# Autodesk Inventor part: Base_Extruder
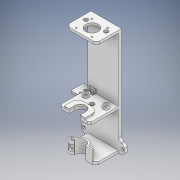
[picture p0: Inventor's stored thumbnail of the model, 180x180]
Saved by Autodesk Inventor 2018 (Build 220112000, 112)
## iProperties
Part Number: Base_Extruder
Material: Plástico ABS
Document SubType Name: Modeling
Designer: ULISES
Density: 1.06 g/cm^3
Appearance: Valor por defecto(1)
Mass: 170.779 g
Surface Area: 663.504 cm^2
Volume: 161.112 cm^3
Author: ULISES
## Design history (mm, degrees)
sketch "Boceto1"
  geometry: L1 (0, 0)-(60, 0); L2 (60, 0)-(60, 49); L3 (60, 49)-(0, 49); L4 (0, 49)-(0, 0); C1 r 1.6 at (50, 29); C2 r 1.6 at (10, 29); C3 r 12.5 at (30, 21); C4 r 13.5 at (30, -2); C5 r 1.6 at (45.5, 36.5); C6 r 1.6 at (14.5, 36.5); C7 r 1.6 at (45.5, 5.5); C8 r 1.6 at (14.5, 5.5)
  constraints: 8 centre point, 8 end point, 2 horizontal, 2 parallel, 1 horizontal alignment, 1 perpendicular, 1 vertical, 1 vertical alignment, 6 other
  dimensions: "d0" = 3.2 diameter of C1; "d1" = 3.2 diameter of C2 (= d0); "d2" = 25 diameter of C3; "d3" = 27 diameter of C4; "d10" = 20 horizontal distance of C3.centre C2.centre (= 0.5 x d15); "d14" = 60 distance of L2.end L3.end; "d15" = 40 distance of C2.centre C1.centre; "d16" = 10 distance from line of L4 C2.centre (= 0.5 x d14 - 0.5 x d15); "d17" = 3.2 diameter of C5; "d20" = 31 distance of C5.centre C6.centre; "d23" = 31 distance of C5.centre C7.centre; "d26" = 15.5 horizontal distance of C5.centre C3.centre (= 0.5 x d20); "d27" = 15.5 horizontal distance of C5.centre C3.centre (= 0.5 x d23); "d47" = 23 distance of C4.centre C3.centre; "d48" = 49 distance of L3.end L1.start; "d50" = 28 distance from line of L3 C3.centre; "d51" = 20 distance from line of L3 C1.centre; "d52" = 8 vertical distance of C3.centre C1.centre (derived)
extrude "Extrusión1" new body sketch "Boceto1" distance "d28" = 5; taper "d29" = 0 deg
sketch "Boceto2"
  geometry: C1 r 1.6 at (10, 29) reference; C2 r 1.6 at (50, 29) reference; C3 r 4.15 at (10, 29); C4 r 4.15 at (50, 29); 1 further point
  constraints: 2 centre point, 2 coincident
  dimensions: "d32" = 8.3 diameter of C3; "d33" = 8.3 diameter of C4
extrude "Extrusión2" cut sketch "Boceto2" distance "d30" = 6; taper "d31" = 0 deg
sketch "Boceto3"
  geometry: L1 (0, 0)-(-60, 0) reference; L2 (0, 49)-(0, 0) reference; L3 (-60, 49)-(0, 49) reference; L4 (-60, 0)-(-60, 49) reference; L5 (-60, 0)-(-60, 49) reference; L6 (-60, 49)-(0, 49); L7 (0, 49)-(0, 43); L8 (0, 43)-(-60, 43); L9 (-60, 43)-(-60, 49); C1 r 12.5 at (-30, 21) reference; C2 r 1.6 at (-14.5, 5.5) reference; C3 r 1.6 at (-45.5, 5.5) reference; C4 r 1.6 at (-14.5, 36.5) reference; C5 r 1.6 at (-45.5, 36.5) reference; 1 further point
  constraints: 8 end point, 2 parallel, 1 horizontal, 1 perpendicular, 1 point on line
  dimensions: "d34" = 6 distance between parallel lines of L3 L8
extrude "Extrusión3" join sketch "Boceto3" distance "d35" = 125; taper "d36" = 0 deg
sketch "Boceto4"
  geometry: L1 (0, 43)-(-60, 43) reference; L2 (-60, 0)-(-60, 43) reference; L3 (0, 0)-(-60, 0) reference; L4 (0, 43)-(0, 0) reference; L5 (0, 43)-(0, 49) reference; L6 (0, 49)-(-60, 49) reference; L7 (-60, 49)-(-60, 43) reference; L8 (-60, 43)-(0, 43) reference; L9 (-60, 0)-(-60, -13); L10 (-60, -13)-(0, -13); L11 (0, -13)-(0, 0); L12 (0, 0)-(-19.285, 0); L13 (-40.715, 0)-(-60, 0); L14 (0, 49)-(0, 0) reference; L15 (0, 0)-(0, 49); L16 (0, 49)-(-60, 49); L17 (-60, 49)-(-60, 0); L18 (-60, 0)-(-40.715, 0); L19 (-19.285, 0)-(0, 0); L20 (-30, -2)-(-40.9, -2); L21 (-40.9, -2)-(-40.9, -13); L22 (-40.9, -13)-(-30, -13); L23 (-30, -13)-(-30, -2); L24 (-30, -2)-(-19.1, -2); L25 (-19.1, -2)-(-19.1, -13); L26 (-19.1, -13)-(-30, -13); L27 (-30, -13)-(-30, -2); C1 r 12.5 at (-30, 21) reference; C2 r 1.6 at (-14.5, 5.5) reference; C3 r 1.6 at (-45.5, 5.5) reference; C4 r 1.6 at (-14.5, 36.5) reference; C5 r 1.6 at (-45.5, 36.5) reference; C6 r 4.5 at (-30, 21); A1 r 10.9 centre (-30, -2) between (-19.285, 0) and (-40.715, 0)
  constraints: 36 end point, 10 parallel, 6 horizontal, 6 perpendicular, 2 centre point, 2 collinear, 2 point on circle, 2 tangent, 1 coincident, 1 point on line, 1 vertical alignment
  dimensions: "d37" = 9 diameter of C6; "d54" = 13 distance of L9.start L9.end; "d55" = 60 distance of L9.end L10.end; "d62" = 23 distance of L20.start C1.centre; "d63" = 21.8 diameter of A1
extrude "Extrusión4" join sketch "Boceto4" distance "d39" = 5; taper "d40" = 0 deg
sketch "Boceto5"
  geometry: C1 r 4.15 at (-10, 29) reference; C2 r 4.15 at (-50, 29) reference; C3 r 6.15 at (-10, 29); C4 r 6.15 at (-50, 29); 1 further point
  constraints: 2 centre point
  dimensions: "d175" = 2 radial gap between concentric circles of C3 C1; "d176" = 2 radial gap between concentric circles of C2 C4
extrude "Extrusión5" join sketch "Boceto5" distance "d41" = 10; taper "d42" = 0 deg
sketch "Boceto6"
  geometry: L1 (-60, 43)-(0, 43) reference; L2 (-60, 43)-(0, 43); L3 (0, 43)-(0, 49); L4 (0, 49)-(-60, 49); L5 (-60, 49)-(-60, 43); L6 (-60, -13)-(-40.9, -13) reference; L7 (0, -13)-(0, 49) reference; L8 (0, 49)-(-60, 49) reference; L9 (-60, 49)-(-60, -13) reference; L10 (-40.9, -13)-(-40.9, -2) reference; L11 (-19.1, -2)-(-19.1, -13) reference; L12 (-19.1, -13)-(0, -13) reference; L13 (-40.9, -2)-(-19.1, -2) reference; C1 r 4.5 at (-30, 21) reference; 1 further point
  constraints: 8 end point, 2 parallel, 1 horizontal, 1 perpendicular
extrude "Extrusión6" join sketch "Boceto6" distance "d43" = 70; taper "d44" = 0 deg
sketch "Boceto7"
  geometry: L1 (0, 43)-(-60, 43) reference; L2 (-60, 43)-(0, 43) reference; L3 (0, 43)-(0, 49) reference; L4 (0, 49)-(-60, 49) reference; L5 (-60, 49)-(-60, 43) reference; L6 (-60, -13)-(-40.9, -13) reference; L7 (-60, 43)-(-60, -13) reference; L8 (0, -13)-(0, 43) reference; L9 (-40.9, -13)-(-40.9, -2) reference; L10 (-19.1, -2)-(-19.1, -13) reference; L11 (-60, -13)-(-40.9, -13) reference; L12 (-40.9, -2)-(-60, -2); L13 (-19.1, -2)-(0, -2); L14 (-60, 49)-(0, 49) reference; L15 (0, -2)-(0, 49); L16 (0, 49)-(-60, 49); L17 (-60, 49)-(-60, -2); L18 (-60, -2)-(-40.9, -2); L19 (-19.1, -2)-(0, -2); L20 (-19.1, -13)-(0, -13) reference; L21 (-40.9, -2)-(-19.1, -2) reference; C1 r 4.5 at (-30, 21) reference; A1 r 10.9 centre (-30, -2) between (-19.1, -2) and (-40.9, -2); 1 further point
  constraints: 14 end point, 3 horizontal, 3 parallel, 2 perpendicular, 2 point on circle, 1 centre point
  dimensions: "d177" = 10.9 radius of A1
extrude "Extrusión7" join sketch "Boceto7" distance "d45" = 5; taper "d46" = 0 deg
sketch "Boceto8"
  geometry: C1 r 1.6 at (-45.5, 5.5) reference; C2 r 1.6 at (-45.5, 36.5) reference; C3 r 1.6 at (-14.5, 36.5) reference; C4 r 1.6 at (-14.5, 5.5) reference; C5 r 3 at (-45.5, 5.5); C6 r 3 at (-45.5, 36.5); C7 r 3 at (-14.5, 36.5); C8 r 1.6 at (-14.5, 5.5) reference; C9 r 3 at (-14.5, 5.5); 1 further point
  constraints: 4 centre point, 4 coincident
  dimensions: "d56" = 6 diameter of C5; "d57" = 6 diameter of C6; "d58" = 6 diameter of C7; "d59" = 6 diameter of C9
extrude "Extrusión8" cut sketch "Boceto8" distance "d60" = 2.5; taper "d61" = 0 deg
sketch "Boceto9"
  geometry: L1 (18.5, 1)-(38.5, 1); L2 (38.5, 11)-(21.5, 11); L3 (48.5, 1)-(48.5, -13); L4 (11.5, -13)-(11.5, 1); L5 (9.5, -13)-(9.5, 1); L6 (21.5, 13)-(38.5, 13); L7 (50.5, 1)-(50.5, -13); L8 (48.5, -13)-(50.5, -13); L9 (9.5, -13)-(11.5, -13); L10 (19.1, -2)-(40.9, -2) reference; L11 (19.1, -13)-(19.1, -2) reference; L12 (19.1, -13)-(0, -13) reference; L13 (60, -13)-(40.9, -13) reference; L14 (40.9, -2)-(40.9, -13) reference; A1 r 10 centre (38.5, 1) between (48.5, 1) and (38.5, 11); A2 r 10 centre (21.5, 1) between (21.5, 11) and (11.5, 1); A3 r 12 centre (21.5, 1) between (21.5, 13) and (9.5, 1); A4 r 12 centre (38.5, 1) between (50.5, 1) and (38.5, 13); 1 further point
  constraints: 19 end point, 8 point on circle, 4 centre point, 4 tangent, 2 collinear, 2 parallel, 1 point on line, 4 other
  dimensions: "d64" = 20 distance of L1.start L1.end; "d66" = 2 radial gap between concentric circles of A1 A4; "d183" = 37 distance between parallel lines of L3 L4; "d184" = 21.8 distance between parallel lines of L14 L11 (derived); "d185" = 7.6 distance between parallel lines of L4 L11 (= 0.5 x d183 - 0.5 x d184); "d186" = 13 distance between parallel lines of L10 L2; "d187" = 10 radius of A2; "d188" = 10 radius of A1
extrude "Extrusión9" join sketch "Boceto9" distance "d67" = 2.2; taper "d68" = 0 deg
sketch "Boceto11" dims "d104" = 10.9 (derived)
  geometry: L1 (44, -2)-(54, -2); L2 (54, -2)-(54, 1); L3 (54, 1)-(43.572, 1); L4 (44, 1)-(44, -2); L5 (19.1, -2)-(9.1, -2); L6 (9.1, -2)-(9.1, 3); L7 (9.1, 3)-(17.03, 3); L8 (19.1, -2)-(0, -2) reference; L9 (19.1, -2)-(9.1, -2); L10 (9.1, -2)-(9.1, -7); L11 (9.1, -7)-(19.1, -7); L12 (19.1, -7)-(19.1, -2); L13 (60, -2)-(40.9, -2) reference; L14 (44, -2)-(40.9, -2); A1 r 13.9 centre (30, -2) between (43.572, 1) and (17.03, 3); 2 further points
  constraints: 24 end point, 4 horizontal, 4 parallel, 3 perpendicular, 2 point on circle, 1 centre point, 1 collinear, 1 vertical, 2 other
  dimensions: "d71" = 3 dimension on A1; "d72" = 3 distance of L1.end L2.end; "d73" = 10 distance of L2.end L4.start; "d75" = 5 distance of L5.end L6.end; "d84" = 10 distance from line of L6 L5.start; "d106" = 5 distance of L9.end L10.end; "d107" = 10 distance of L10.end L11.end
extrude "Extrusión11" join sketch "Boceto11" distance "d76" = 20; taper "d77" = 0 deg
node "Plano de trabajo1"
sketch "Boceto13"
  geometry: L1 (0, 49)-(-60, 49) reference; L2 (-60, 49)-(-60, -2) reference; L3 (-60, -2)-(-40.9, -2) reference; L4 (-19.1, -2)-(0, -2) reference; L5 (0, -2)-(0, 49) reference; L6 (-9.1, -2)-(-9.1, 3) reference; L7 (-19.1, -2)-(0, -2) reference; L8 (-17.03, 3)-(-9.1, 3) reference; L9 (-9.1, 3)-(-17.03, 3); L10 (-9.1, 3)-(-9.1, -7) reference; L11 (-9.1, 3)-(-9.1, -2); L12 (-9.1, -2)-(-21.1, -2); L13 (-21.1, -2)-(-21.1, -7); L14 (-21.1, -7)-(-9.1, -7); L15 (-9.1, -7)-(-9.1, -2); C1 r 4 at (-14.1, -2); C2 r 1.7 at (-14.1, -2); A1 r 10.9 centre (-30, -2) between (-19.1, -2) and (-40.9, -2) reference; A2 r 13.9 centre (-30, -2) between (-17.03, 3) and (-43.572, 1) reference; 1 further point
  constraints: 12 end point, 2 centre point, 2 horizontal, 2 parallel, 2 perpendicular, 1 coincident, 1 collinear
  dimensions: "d85" = 0 distance from line of L4 C1.centre; "d86" = 5 distance from line of L6 C1.centre; "d87" = 8 diameter of C1; "d88" = 3.4 diameter of C2; "d90" = 12 distance between parallel lines of L10 L13; "d108" = 5 distance of L12.end L13.end
extrude "Extrusión12" cut sketch "Boceto13" distance "d91" = 12; taper "d92" = 0 deg
sketch "Boceto14"
  geometry: L1 (40.9, -2)-(54, -2) reference; L2 (54, -2)-(54, 1) reference; L3 (54, 1)-(43.572, 1) reference; L4 (17.03, 3)-(9.1, 3) reference; L5 (9.1, 3)-(9.1, -7) reference; L6 (9.1, -7)-(19.1, -7) reference; L7 (19.1, -7)-(19.1, -2) reference; C1 r 1.75 at (14.1, -2); A1 r 13.9 centre (30, -2) between (43.572, 1) and (17.03, 3) reference; A2 r 10.9 centre (30, -2) between (40.9, -2) and (19.1, -2) reference; 1 further point
  constraints: 1 centre point
  dimensions: "d93" = 5 distance from line of L4 C1.centre; "d94" = 5 distance from line of L5 C1.centre; "d95" = 3.5 diameter of C1
extrude "Extrusión13" cut sketch "Boceto14" distance "d96" = 45.5; taper "d97" = 0 deg
sketch "Boceto15"
  geometry: L1 (16.886, -3.857)-(13.884, -5.342); L2 (13.884, -5.342)-(11.098, -3.484); L3 (11.098, -3.484)-(11.314, -0.143); L4 (11.314, -0.143)-(14.316, 1.342); L5 (14.316, 1.342)-(17.102, -0.516); L6 (17.102, -0.516)-(16.886, -3.857); C1 r 1.75 at (14.1, -2) reference; 2 further points
  constraints: 12 end point, 1 coincident, 13 other
  dimensions: "d98" = 5.8 distance between parallel lines of L3 L6
extrude "Extrusión14" cut sketch "Boceto15" distance "d99" = 4; taper "d100" = 0 deg
sketch "Boceto17"
  geometry: L1 (-19.1, -7)-(-19.1, -2) reference; L2 (-9.1, -7)-(-19.1, -7) reference; L3 (-9.1, -2)-(-9.1, -7) reference; L4 (-12.35, -2)-(-9.1, -2) reference; L5 (-19.1, -2)-(-15.85, -2) reference; A1 r 1.75 centre (-14.1, -2) between (-15.85, -2) and (-12.35, -2) reference; 1 further point
extrude "Extrusión16" join sketch "Boceto17" distance "d109" = 5; taper "d110" = 0 deg
sketch "Boceto16"
  geometry: C1 r 1.75 at (-14.1, -2) reference; C2 r 3 at (-14.1, -2); 1 further point
  constraints: 1 centre point, 1 coincident
  dimensions: "d101" = 6 diameter of C2
extrude "Extrusión15" cut sketch "Boceto16" distance "d102" = 4; taper "d103" = 0 deg
fillet "Empalme1" dims "d111" = 5
chamfer "Chaflán1" distance "d112" = 6; stored, may be unused: second distance "d113" = 2, angle "d114" = 45 deg
chamfer "Chaflán2" distance "d115" = 4; stored, may be unused: second distance "d116" = 2, angle "d117" = 45 deg
chamfer "Chaflán3" distance "d118" = 6; stored, may be unused: second distance "d119" = 2, angle "d120" = 45 deg
sketch "Boceto18"
  geometry: L1 (0, -52)-(0, 0) reference; L2 (-5, -52)-(-5, 0) reference; L3 (-80, 6)-(130, 6) reference; L4 (0, -19)-(-5, -19); L5 (-5, -19)-(-5, 6); L6 (-5, 6)-(0, 6); L7 (0, 6)-(0, -19); 2 further points
  constraints: 8 end point, 3 point on line, 2 parallel, 1 horizontal, 1 perpendicular
  dimensions: "d121" = 25 distance between parallel lines of L3 L4
extrude "Extrusión17" join sketch "Boceto18" distance "d122" = 14; taper "d123" = 0 deg
sketch "Boceto19"
  geometry: L1 (0, 49)-(-14, 49) reference; L2 (0, 49)-(0, 6) reference; C1 r 1.6 at (-1.6, 29); C2 r 1.6 at (-1.6, 39); 1 further point
  constraints: 2 centre point, 1 vertical alignment
  dimensions: "d124" = 3.2 diameter of C1; "d125" = 3.2 diameter of C2; "d126" = 10 distance from line of L1 C2.centre; "d127" = 10 distance of C2.centre C1.centre; "d128" = 1.6 distance from line of L2 C2.centre (= 0.5 x d125)
extrude "Extrusión18" cut sketch "Boceto19" distance "d129" = 15; taper "d130" = 0 deg
sketch "Boceto20"
  geometry: L1 (0, 5)-(-14, 5) reference; L2 (0, 5)-(-14, 5) reference; A1 r 25 centre (-7, 29) between (-14, 5) and (0, 5); 1 further point
  constraints: 2 point on circle, 1 centre point
extrude "Extrusión19" cut sketch "Boceto20" distance "d131" = 25; taper "d132" = 0 deg
sketch "Boceto21"
  geometry: L1 (3.75, -125)-(16.25, -125); L2 (16.25, -125)-(16.25, -117); L3 (16.25, -117)-(3.75, -117); L4 (3.75, -117)-(3.75, -125); L5 (19.1, -125)-(11.5, -125) reference; L6 (60, -125)-(0, -125) reference; L7 (0, 0)-(0, -125) reference
  constraints: 8 end point, 2 collinear, 2 parallel, 1 horizontal, 1 perpendicular
  dimensions: "d133" = 8 distance of L1.end L2.end; "d134" = 12.5 distance of L2.end L3.end; "d189" = 3.75 distance between parallel lines of L7 L4
extrude "Extrusión20" join sketch "Boceto21" distance "d137" = 1.5; taper "d138" = 0 deg
sketch "Boceto22"
  geometry: L1 (16.25, -125)-(16.25, -117) reference; L2 (16.25, -117)-(3.75, -117) reference; L3 (3.75, -117)-(3.75, -125) reference; L4 (16.25, -125)-(3.75, -125) reference; C1 r 1 at (6.75, -122); C2 r 1 at (13.25, -122); 1 further point
  constraints: 2 centre point, 1 horizontal alignment
  dimensions: "d139" = 6.5 distance of C1.centre C2.centre; "d140" = 3 distance from line of L3 C1.centre (= 0.5 x d144 - 0.5 x d139); "d142" = 2 diameter of C2; "d143" = 2 diameter of C1; "d144" = 12.5 distance of L1.end L2.end (derived); "d205" = 3 distance from line of L4 C1.centre
extrude "Extrusión21" cut sketch "Boceto22" distance "d145" = 5; taper "d146" = 0 deg
sketch "Boceto26"
  geometry: L1 (60, -75)-(60, 135) reference; L2 (60, -75)-(72.25, -75); L3 (72.25, -75)-(72.25, -55); L4 (72.25, -55)-(60, -55); L5 (60, -55)-(60, -75); L6 (0, -75)-(-12.25, -75); L7 (-12.25, -75)-(-12.25, -55); L8 (-12.25, -55)-(0, -55); L9 (0, -55)-(0, -75); L10 (0, 0)-(0, -70) reference; 2 further points
  constraints: 16 end point, 4 parallel, 2 horizontal, 2 perpendicular, 2 point on line, 1 collinear
  dimensions: "d166" = 12.25 distance of L3.end L4.end; "d167" = 20 distance of L2.end L3.end; "d168" = 12.25 distance of L7.end L8.end; "d169" = 20 distance of L6.end L7.end (derived)
extrude "Extrusión24" join sketch "Boceto26" distance "d170" = 6; taper "d171" = 0 deg
sketch "Boceto23"
  geometry: L1 (60, 205)-(0, 205) reference; L2 (0, 135)-(60, 135) reference; L3 (60, 205)-(60, 0) reference; C1 r 1.7 at (-8, 200); C2 r 1.7 at (68, 200); C3 r 1.7 at (30, 140.75); 3 further points
  constraints: 3 centre point, 1 horizontal alignment
  dimensions: "d147" = 76 distance of C2.centre C1.centre; "d148" = 38 horizontal distance of C1.centre C3.centre (= 0.5 x d147); "d149" = 59.25 vertical distance of C1.centre C3.centre; "d150" = 60 distance of L1.start L1.end (derived); "d151" = 70 distance between parallel lines of L1 L2 (derived); "d152" = 5 distance from line of L1 C1.centre; "d154" = 3.4 diameter of C1; "d155" = 3.4 diameter of C2; "d156" = 3.4 diameter of C3; "d164" = 60 distance of L2.start L2.end (derived); "d165" = 30 distance from line of L3 C3.centre (= 0.5 x d164)
extrude "Extrusión22" cut sketch "Boceto23" distance "d157" = 10; taper "d158" = 0 deg
sketch "Boceto25"
  geometry: L1 (31.703, -8.7)-(28.297, -8.7); L2 (28.297, -8.7)-(26.594, -5.75); L3 (26.594, -5.75)-(28.297, -2.8); L4 (28.297, -2.8)-(31.703, -2.8); L5 (31.703, -2.8)-(33.406, -5.75); L6 (33.406, -5.75)-(31.703, -8.7); L7 (69.703, -67.95)-(66.297, -67.95); L8 (66.297, -67.95)-(64.594, -65); L9 (64.594, -65)-(66.297, -62.05); L10 (66.297, -62.05)-(69.703, -62.05); L11 (69.703, -62.05)-(71.406, -65); L12 (71.406, -65)-(69.703, -67.95); L13 (-9.703, -67.95)-(-11.406, -65); L14 (-11.406, -65)-(-9.703, -62.05); L15 (-9.703, -62.05)-(-6.297, -62.05); L16 (-6.297, -62.05)-(-4.594, -65); L17 (-4.594, -65)-(-6.297, -67.95); L18 (-6.297, -67.95)-(-9.703, -67.95); C1 r 1.7 at (30, -5.75) reference; C2 r 1.7 at (68, -65) reference; C3 r 1.7 at (-8, -65) reference; C4 r 1.7 at (-8, -65) reference; 4 further points
  constraints: 36 end point, 3 coincident, 3 horizontal, 39 other
  dimensions: "d159" = 5.9 distance between parallel lines of L18 L15; "d160" = 5.9 distance between parallel lines of L7 L10; "d161" = 5.9 distance between parallel lines of L1 L4
extrude "Extrusión23" cut sketch "Boceto25" distance "d162" = 2.5; taper "d163" = 0 deg
sketch "Boceto27"
  geometry: L1 (48.5, -13)-(48.5, 1) reference; L2 (38.5, 11)-(21.5, 11) reference; L3 (11.5, 1)-(11.5, -13) reference; L4 (19.1, -13)-(11.5, -13) reference; L5 (19.1, -13)-(19.1, -2) reference; L6 (19.1, -2)-(40.9, -2) reference; L7 (40.9, -2)-(40.9, -13) reference; L8 (48.5, -13)-(40.9, -13) reference; L9 (21.5, 11)-(38.5, 11) reference; L10 (48.5, 1)-(48.5, -13) reference; L11 (48.5, -13)-(50.5, -13) reference; L12 (50.5, -13)-(50.5, 1) reference; L13 (38.5, 13)-(21.5, 13) reference; L14 (9.5, 1)-(9.5, -13) reference; L15 (9.5, -13)-(11.5, -13) reference; L16 (11.5, -13)-(11.5, 1) reference; A1 r 10 centre (38.5, 1) between (48.5, 1) and (38.5, 11) reference; A2 r 10 centre (21.5, 1) between (21.5, 11) and (11.5, 1) reference; A3 r 10 centre (38.5, 1) between (48.5, 1) and (38.5, 11) reference; A4 r 12 centre (38.5, 1) between (50.5, 1) and (38.5, 13) reference; A5 r 12 centre (21.5, 1) between (21.5, 13) and (9.5, 1) reference; A6 r 10 centre (21.5, 1) between (21.5, 11) and (11.5, 1) reference; 1 further point
extrude "Extrusión25" join sketch "Boceto27" distance "d173" = 1.5; taper "d174" = 0 deg
sketch "Boceto28"
  geometry: L1 (-19.1, -2)-(-40.9, -2) reference; L2 (-19.4, -2)-(-19.1, -2); L3 (-40.6, -2)-(-40.9, -2); A1 r 10.9 centre (-30, -2) between (-19.1, -2) and (-40.9, -2) reference; A2 r 10.6 centre (-30, -2) between (-19.4, -2) and (-40.6, -2); 1 further point
  constraints: 4 end point, 2 collinear, 2 point on circle, 1 centre point
  dimensions: "d190" = 0.3 radial gap between concentric circles of A1 A2
extrude "Extrusión26" join sketch "Boceto28" distance "d191" = 25; taper "d192" = 0 deg
chamfer "Chaflán4" distance "d193" = 0.3; stored, may be unused: second distance "d194" = 2, angle "d195" = 45 deg
sketch "Boceto29"
  geometry: L1 (-40.9, -2)-(-19.1, -2) reference; C1 r 10.9 at (-30, -2); 1 further point
  constraints: 1 centre point, 1 midpoint
  dimensions: "d196" = 21.8 diameter of C1
extrude "Extrusión27" cut sketch "Boceto29" distance "d197" = 25; taper "d198" = 0 deg
chamfer "Chaflán5" distance "d199" = 5; stored, may be unused: second distance "d200" = 2, angle "d201" = 45 deg
chamfer "Chaflán6" distance "d202" = 5; stored, may be unused: second distance "d203" = 2, angle "d204" = 45 deg
sketch "Boceto30"
  geometry: L1 (0, 43)-(60, 43) reference; L2 (16.25, 41.5)-(3.75, 41.5) reference; L3 (16.25, 40.5)-(0.75, 40.5); L4 (0.75, 40.5)-(0.75, 36.5); L5 (0.75, 36.5)-(16.25, 36.5); L6 (16.25, 36.5)-(16.25, 40.5); 1 further point
  constraints: 8 end point, 2 parallel, 1 horizontal, 1 perpendicular, 1 vertical alignment
  dimensions: "d206" = 15.5 distance of L4.end L5.end; "d207" = 1 distance between parallel lines of L2 L3; "d208" = 4 distance of L5.end L3.start
extrude "Extrusión28" cut sketch "Boceto30" distance "d209" = 25; taper "d210" = 0 deg
node "Sólido1"
node "Contorno proyectado1"
node "Contorno proyectado2"
node "Contorno proyectado3"
node "Contorno proyectado4"
node "Contorno proyectado5"
node "Contorno proyectado6"
node "Contorno proyectado11"
node "Contorno proyectado12"
node "Contorno proyectado13"
node "Contorno proyectado14"
node "Contorno proyectado15"
node "Contorno proyectado16"
other parameters: "d81" = -6
